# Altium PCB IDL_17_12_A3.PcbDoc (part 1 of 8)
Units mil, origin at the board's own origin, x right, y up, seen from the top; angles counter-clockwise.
Board outline 5119.97 x 10350 mil, 6 copper layers (Top Signal, 3.3 Volt, GND, 5 Volt, Split Plane, Bot Signal), stack 66.2 mil thick; 510 components, 178 nets, 2317 pads, 385 vias.
Unrouted connection lines stored in the file: 1.
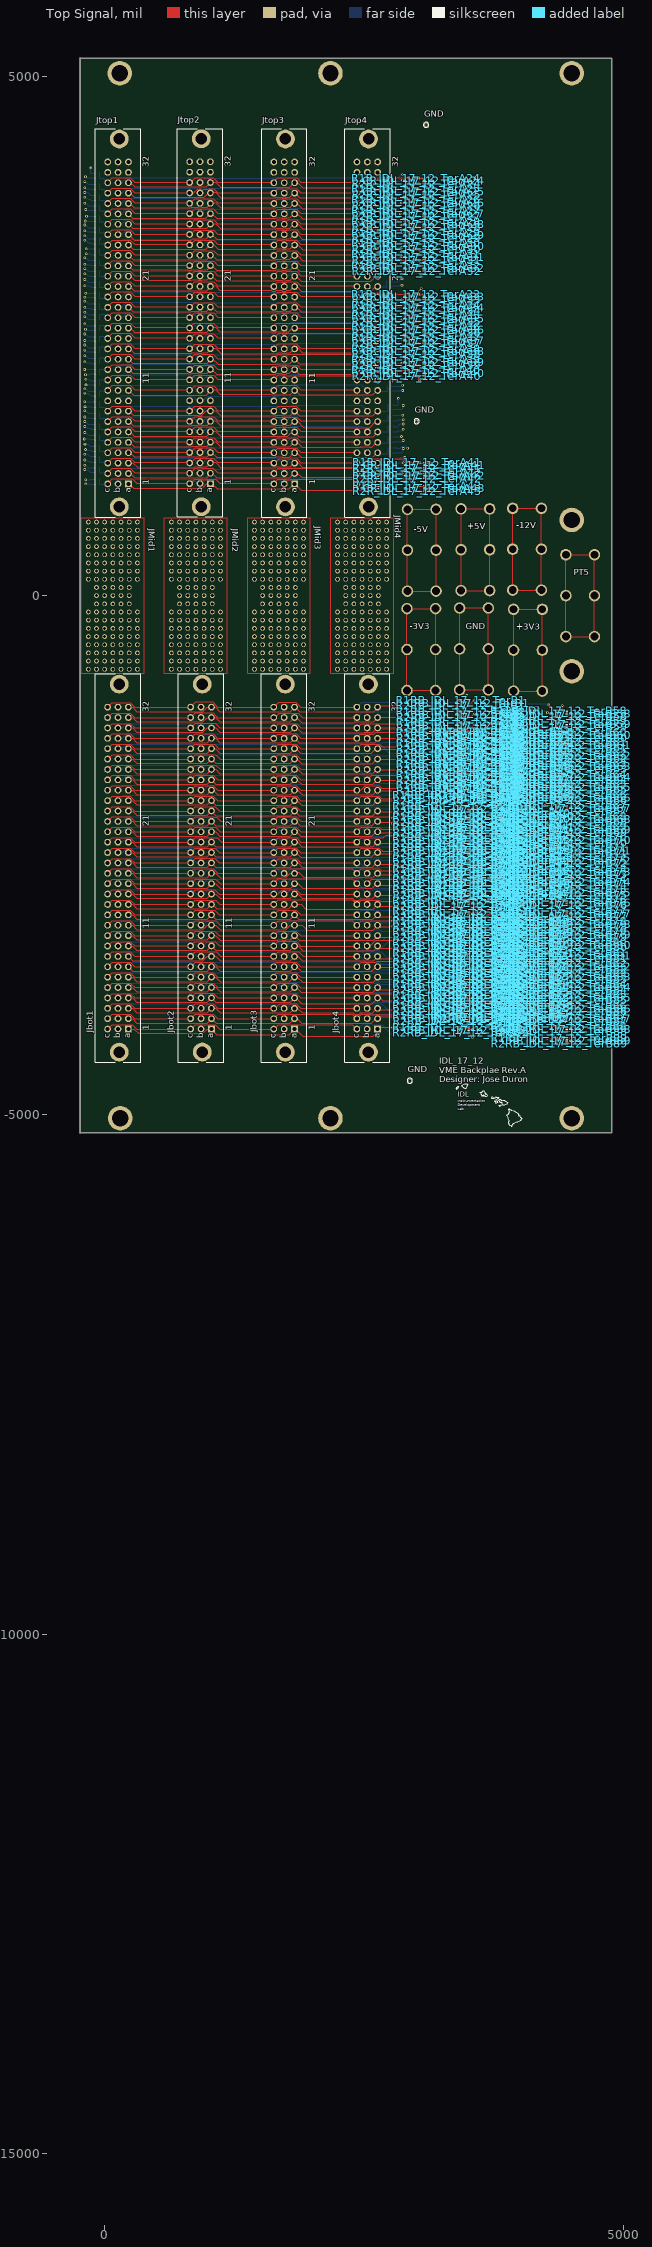
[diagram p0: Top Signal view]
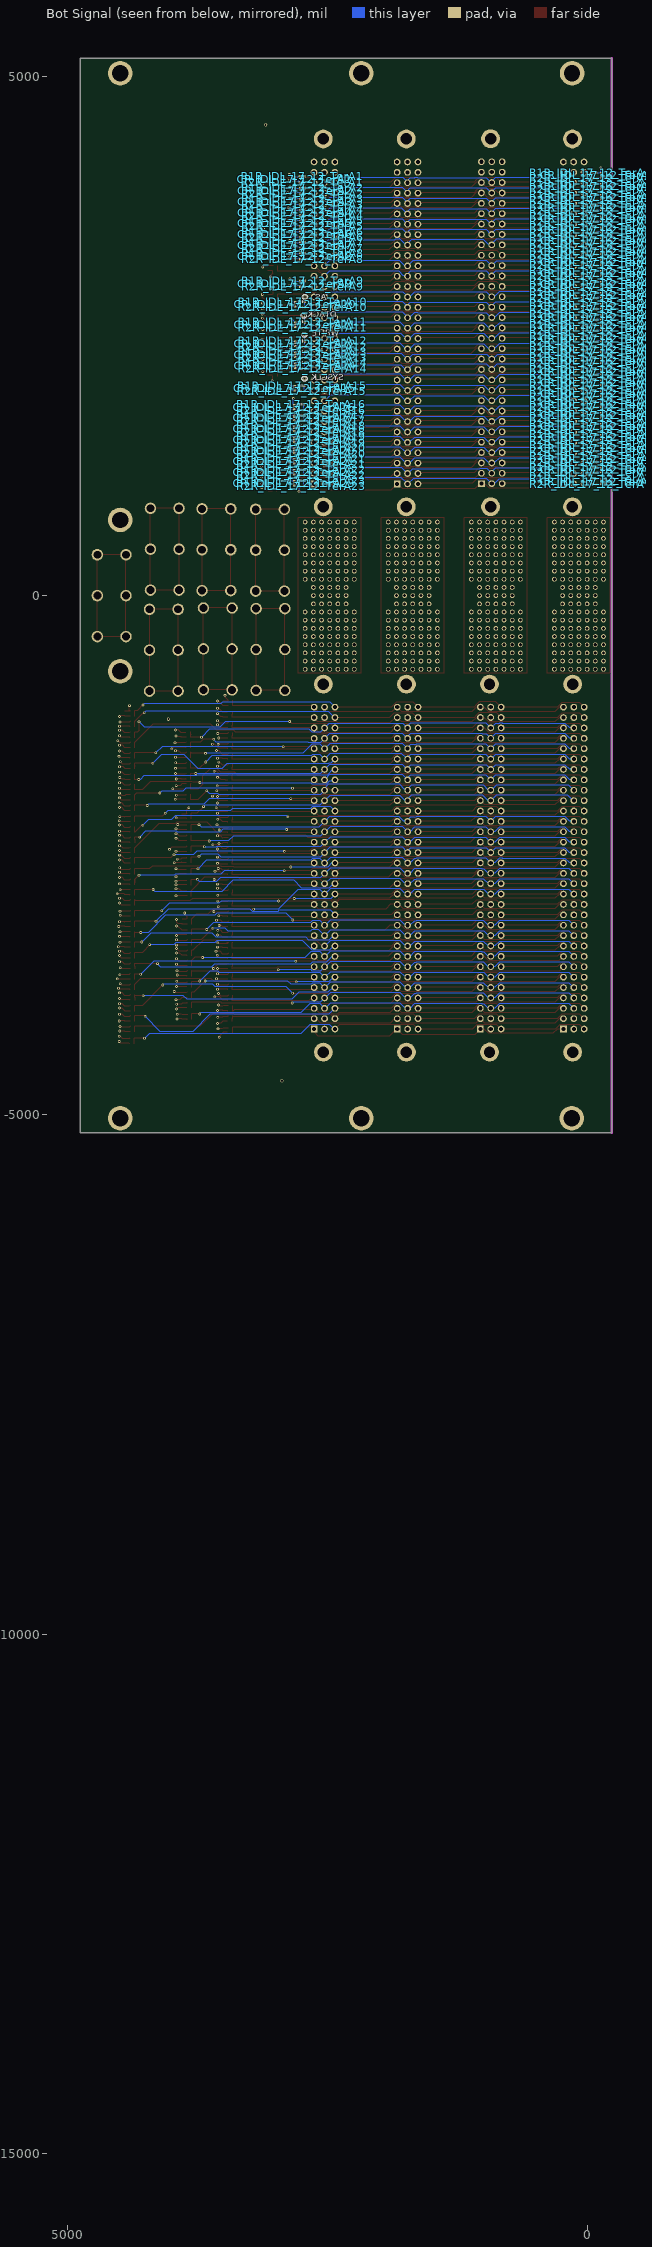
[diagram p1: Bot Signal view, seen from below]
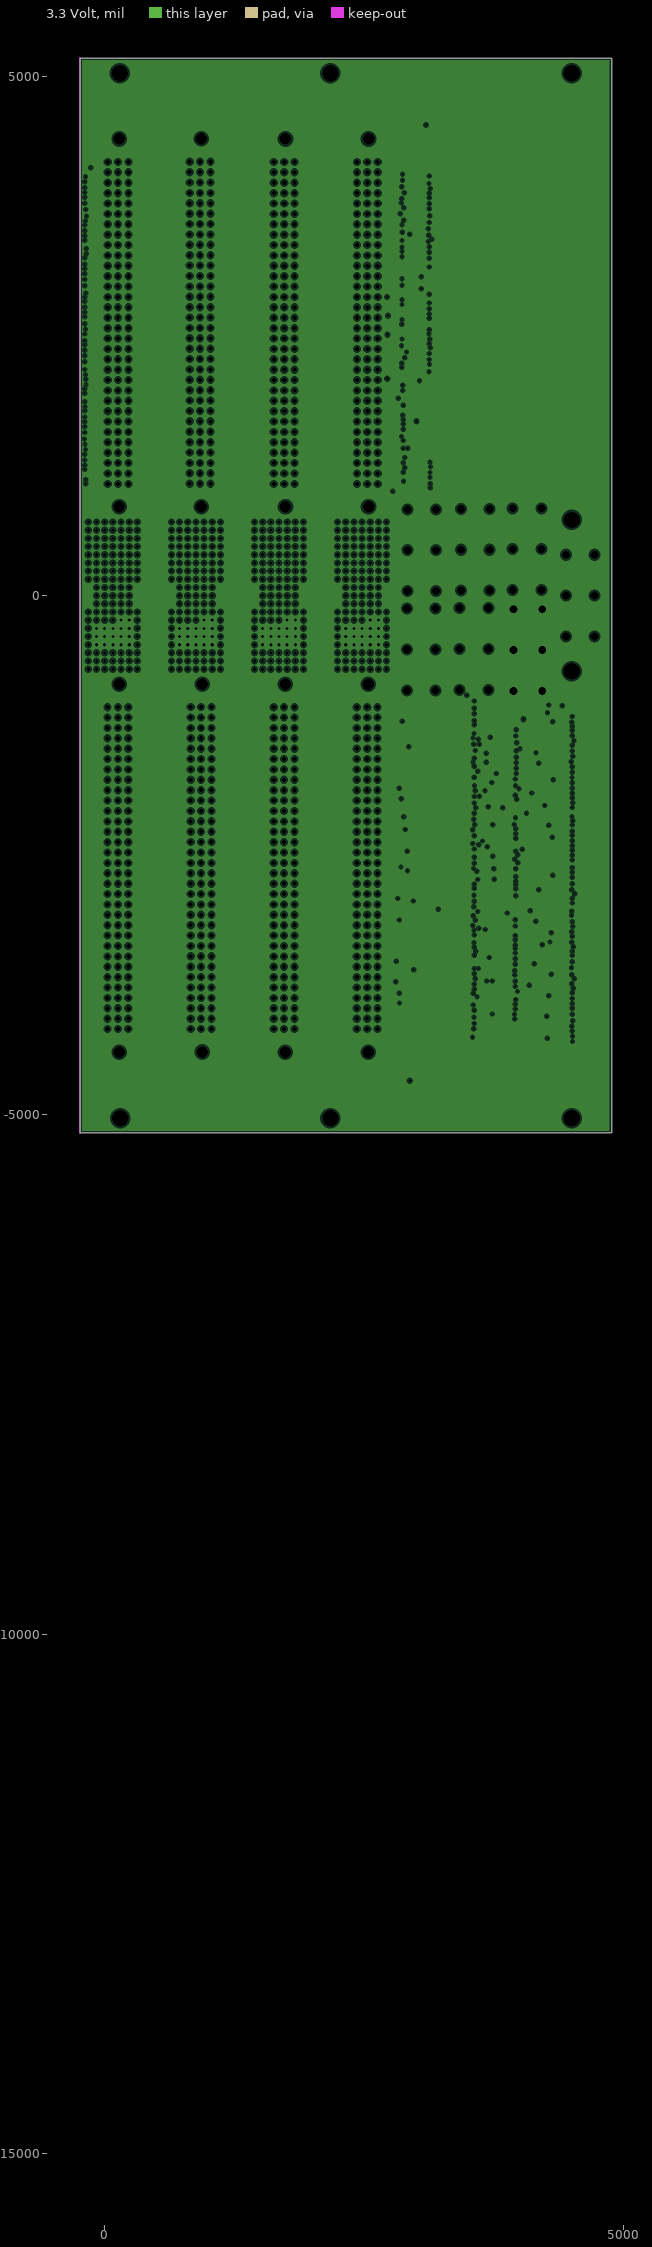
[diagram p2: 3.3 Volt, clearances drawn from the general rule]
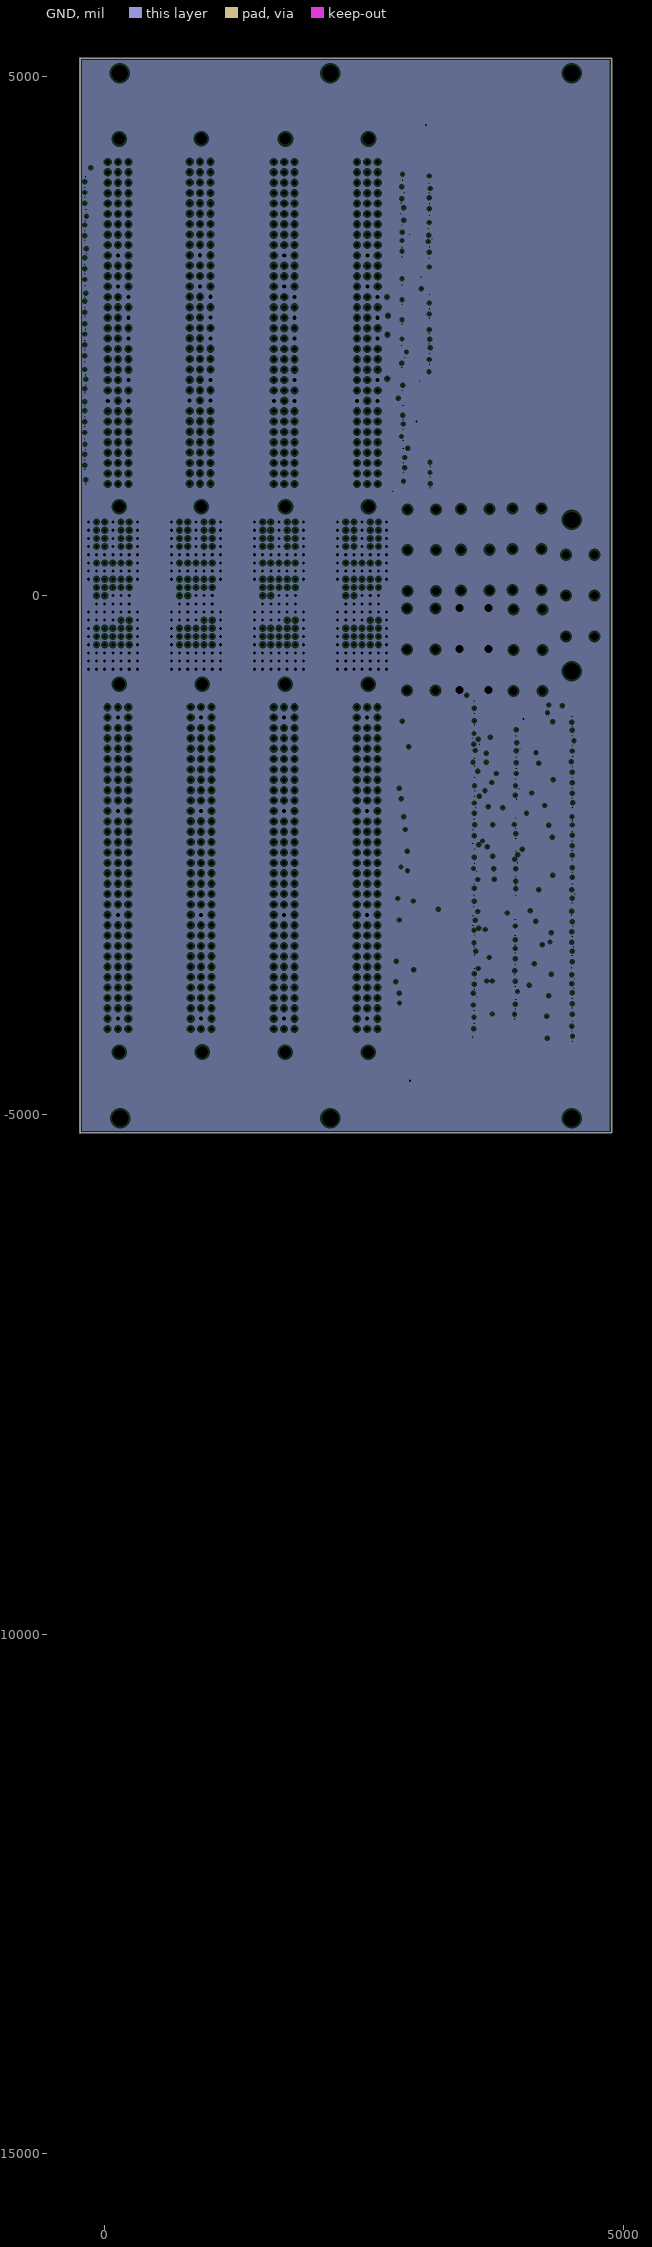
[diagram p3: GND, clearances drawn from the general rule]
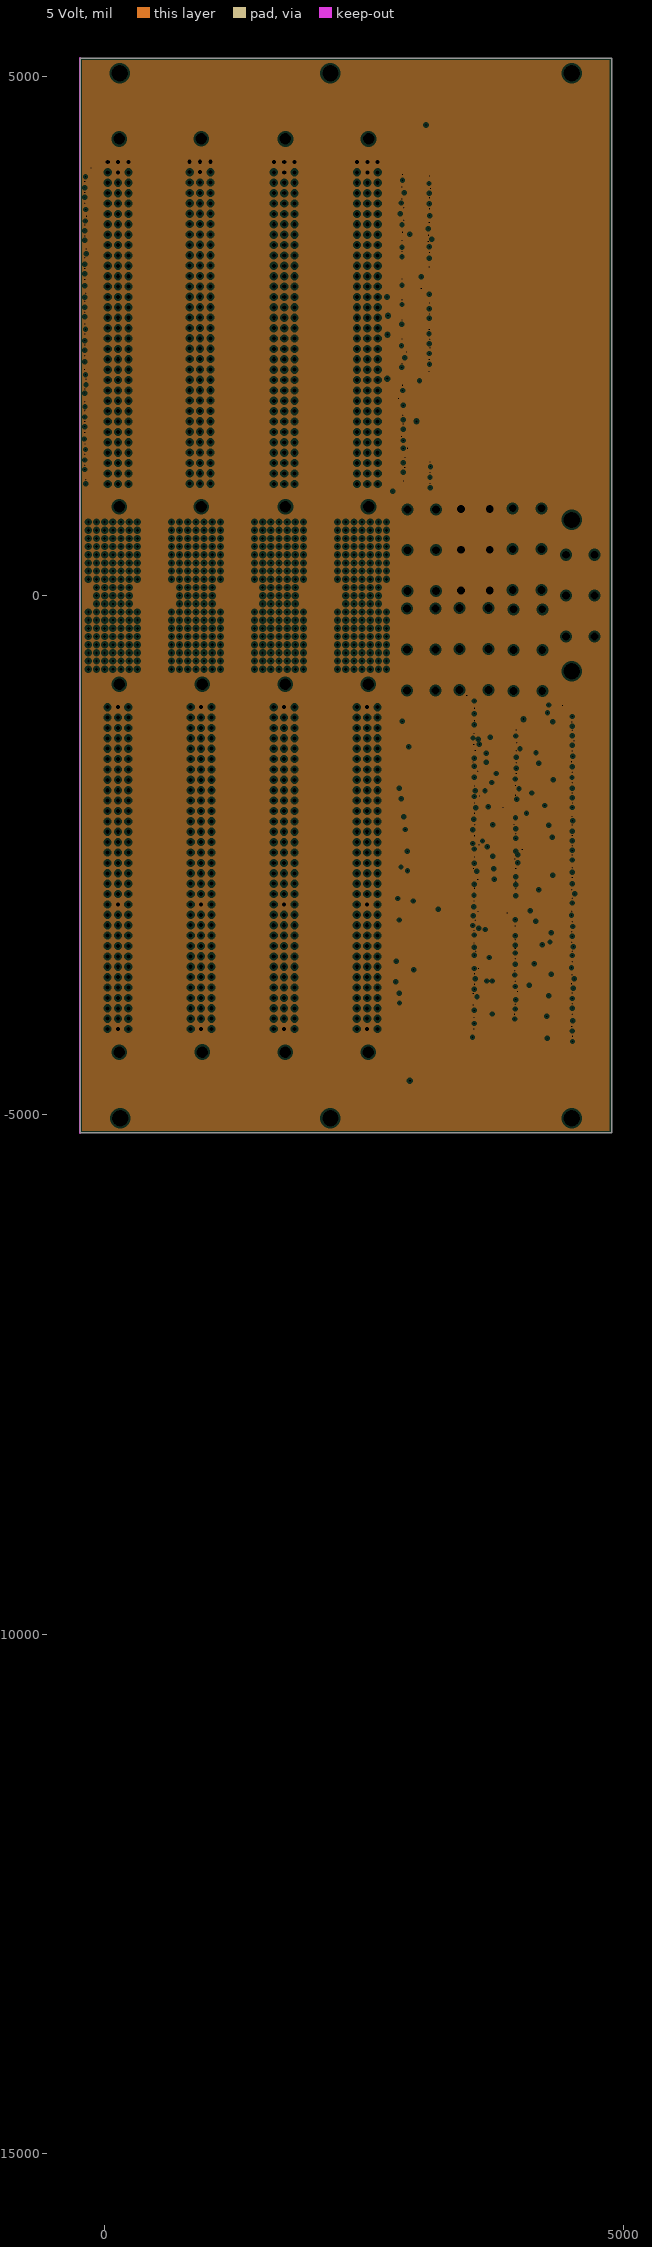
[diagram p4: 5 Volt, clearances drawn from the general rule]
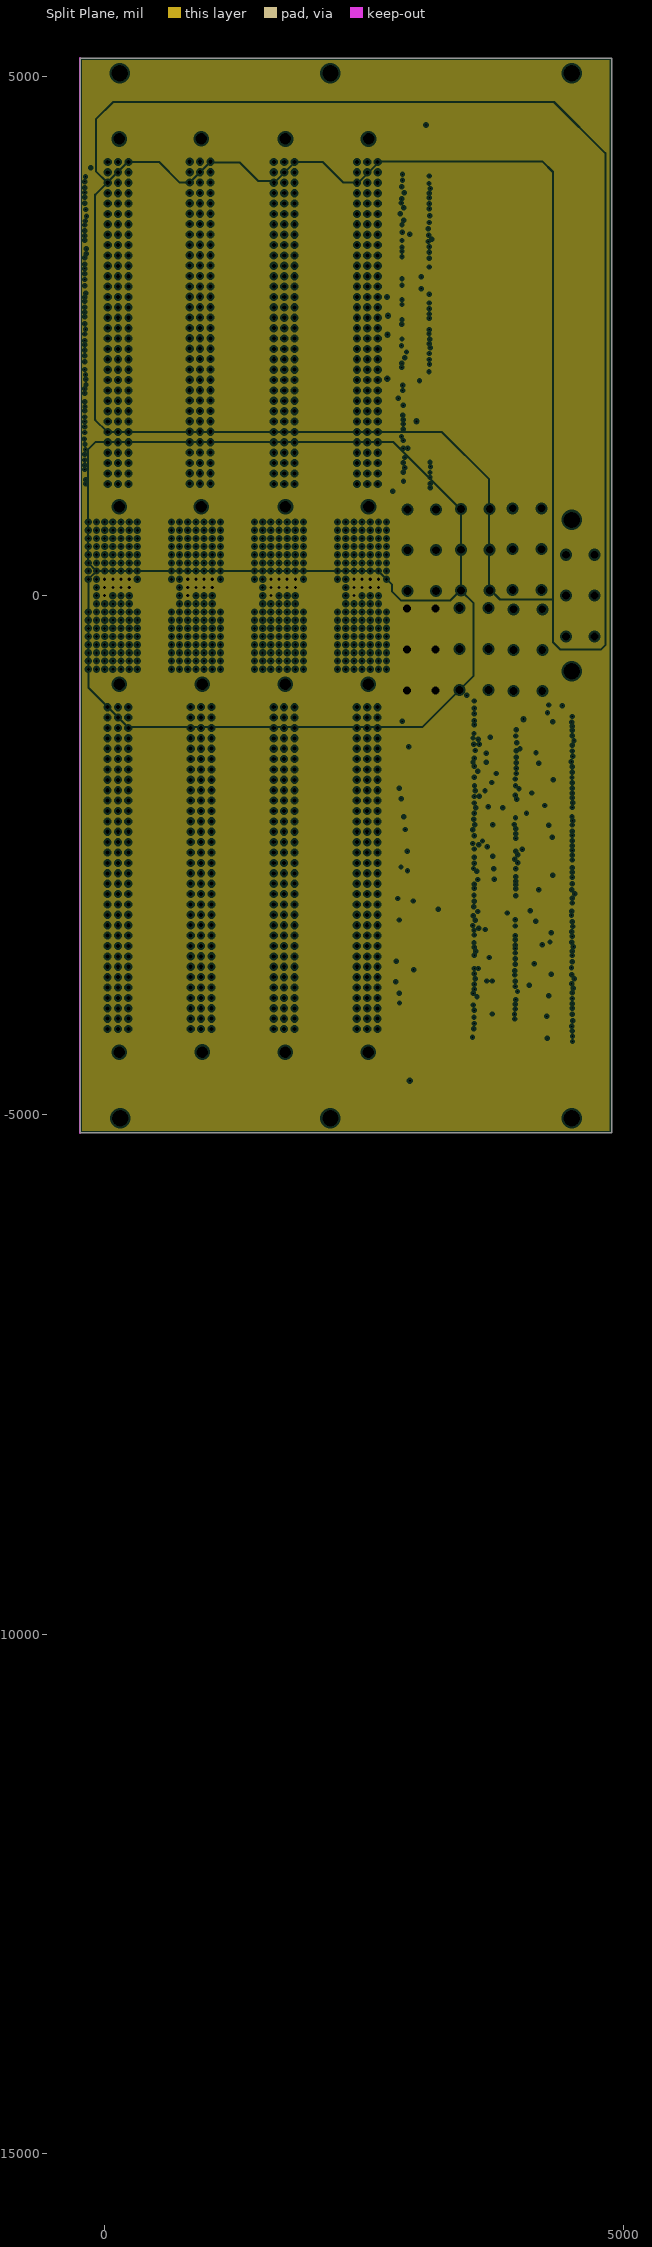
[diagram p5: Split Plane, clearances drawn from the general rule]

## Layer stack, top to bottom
Top Solder: solder mask 0.4, Solder Resist, Dk 3.5
Top Signal: signal copper 2.7
Dielectric 1: core 10, FR-4, Dk 4.2
3.3 Volt: plane copper 2.7, net 3V3
Dielectric2: prepreg 10, FR-4, Dk 4.2
GND: plane copper 2.7, net GND
Dielectric 5: core 10, FR-4, Dk 4.2
5 Volt: plane copper 2.7, net 5V
Dielectric 6: prepreg 10, FR-4, Dk 4.2
Split Plane: plane copper 2.7, net -3V3
Dielectric3: core 10, FR-4, Dk 4.2
Bot Signal: signal copper 2.7
Bottom Solder: solder mask 0.4, Solder Resist, Dk 3.5

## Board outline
-237,5177 4882.97,5177 4882.97,-5173 -237,-5173

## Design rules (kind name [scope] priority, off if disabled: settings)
Clearance "Clearance - Default - DEFAULT- SMD" [IsVia vs IsSMTPin] p1: gap=6 ignorepadtopadclearanceinfootprint=FALSE
Clearance "Clearance - Default - DEFAULT - Via" [IsVia vs IsVia] p2: gap=6 ignorepadtopadclearanceinfootprint=FALSE
Clearance "Clearance - Default - DEFAULT - Net" [All] p3: gap=6 ignorepadtopadclearanceinfootprint=FALSE except(0: Arc-Hole Track-Hole SMDPad-Hole THPad-Hole Via-Hole Fill-Hole Poly-Hole Region-Hole Text-Hole; 10: Text-Text)
ComponentClearance "ComponentClearance - Default - DEFAULT" [All] p1: gap=6 collisioncheckmode=3 verticalgap=10 showdistances=FALSE
DiffPairsRouting [All] p1: maxlimit=10 minlimit=4.02 mostfreqgap=6 toplayer_minwidth=4.02 toplayer_maxwidth=10 toplayer_prefwidth=8 bottomlayer_minwidth=4.02 bottomlayer_maxwidth=10 bottomlayer_prefwidth=8 maxuncoupledlength=500
FanoutControl Fanout_Small [(CompPinCount < 5)] p3: bgadir=Out bgaviamode=Centered fanoutstyle=Auto fanoutdirection=OutThenIn viagrid=1 // Fanout_Small (Default Rule)
FanoutControl Fanout_SOIC [IsSOIC] p4: bgadir=Out bgaviamode=Centered fanoutstyle=Auto fanoutdirection=Alternating viagrid=1 // Fanout_SOIC (Default Rule)
HoleSize [All] p1: absolutevalues=TRUE maxlimit=200 minlimit=1 maxpercent=80.000 minpercent=20.000
HoleToHoleClearance "HoleToHoleClearance - Default - DEFAULT" [All] p1: gap=6 allowstackedmicrovias=TRUE
Length "Default Length" [All] p1: maxlimit=50000 minlimit=0
MaxMinImpedance "Default Impedance" [All] p1: minimum=50.00 maximum=150.0
MinimumSolderMaskSliver [All] p1: minsoldermaskwidth=5
ParallelSegment "Default Parallel Segment Adjasent" [All] p1: limit=1000 gap=200
ParallelSegment "Default Parallel Segment Same Layer" [All] p2: limit=1000 gap=200
PlaneClearance [All] p1: clearance=20
PlaneConnect "Default PlaneConnect" [All] p1: planeconnectstyle=Direct reliefexpansion=20 reliefentries=4 reliefconductorwidth=15 reliefairgap=10
PolygonConnect "PolygonConnect - Default SMT" [IsSMTPin] p1: connectstyle=Relief reliefconductorwidth=10 reliefentries=4 polygonreliefangle="45 Angle" airgapwidth=10
PolygonConnect "PolygonConnect - Default Pad" [All] p2: connectstyle=Relief reliefconductorwidth=15 reliefentries=4 polygonreliefangle="45 Angle" airgapwidth=10
RoomDefinition IDL_17_12_TerA72 [InComponentClass('IDL_17_12_TerA72')] p1 off: confinementstyle=ConfineIn formatcopy=TRUE lockcomponents=FALSE outline 5150.72,878.23 5314.5,878.23 5314.5,997.65 5150.72,997.65
RoomDefinition IDL_17_12_TerB89 [InComponentClass('IDL_17_12_TerB89')] p2 off: confinementstyle=ConfineIn formatcopy=TRUE lockcomponents=TRUE outline 5340.67,-4332.36 5485.36,-4332.36 5485.36,-4220.91 5340.67,-4220.91
RoomDefinition IDL_17_12_TerB88 [InComponentClass('IDL_17_12_TerB88')] p3 off: confinementstyle=ConfineIn formatcopy=TRUE lockcomponents=FALSE outline 5340,-4106.02 5488.48,-4106.02 5488.48,-4214.48 5340,-4214.48
RoomDefinition IDL_17_12_TerB87 [InComponentClass('IDL_17_12_TerB87')] p4 off: confinementstyle=ConfineIn formatcopy=TRUE lockcomponents=FALSE outline 5340,-4006.02 5488.48,-4006.02 5488.48,-4114.48 5340,-4114.48
RoomDefinition IDL_17_12_TerB86 [InComponentClass('IDL_17_12_TerB86')] p5 off: confinementstyle=ConfineIn formatcopy=TRUE lockcomponents=FALSE outline 5340,-3906.02 5488.48,-3906.02 5488.48,-4014.48 5340,-4014.48
RoomDefinition IDL_17_12_TerB85 [InComponentClass('IDL_17_12_TerB85')] p6 off: confinementstyle=ConfineIn formatcopy=TRUE lockcomponents=FALSE outline 5340,-3801.02 5488.48,-3801.02 5488.48,-3909.48 5340,-3909.48
RoomDefinition IDL_17_12_TerB84 [InComponentClass('IDL_17_12_TerB84')] p7 off: confinementstyle=ConfineIn formatcopy=TRUE lockcomponents=FALSE outline 5340,-3701.02 5488.48,-3701.02 5488.48,-3809.48 5340,-3809.48
RoomDefinition IDL_17_12_TerB83 [InComponentClass('IDL_17_12_TerB83')] p8 off: confinementstyle=ConfineIn formatcopy=TRUE lockcomponents=FALSE outline 5340,-3601.02 5488.48,-3601.02 5488.48,-3709.48 5340,-3709.48
RoomDefinition IDL_17_12_TerB82 [InComponentClass('IDL_17_12_TerB82')] p9 off: confinementstyle=ConfineIn formatcopy=TRUE lockcomponents=FALSE outline 5340,-3501.02 5488.48,-3501.02 5488.48,-3609.48 5340,-3609.48
RoomDefinition IDL_17_12_TerB81 [InComponentClass('IDL_17_12_TerB81')] p10 off: confinementstyle=ConfineIn formatcopy=TRUE lockcomponents=FALSE outline 5340,-3399.02 5488.48,-3399.02 5488.48,-3507.48 5340,-3507.48
RoomDefinition IDL_17_12_TerB80 [InComponentClass('IDL_17_12_TerB80')] p11 off: confinementstyle=ConfineIn formatcopy=TRUE lockcomponents=FALSE outline 5340,-3294.02 5488.48,-3294.02 5488.48,-3402.48 5340,-3402.48
RoomDefinition IDL_17_12_TerB79 [InComponentClass('IDL_17_12_TerB79')] p12 off: confinementstyle=ConfineIn formatcopy=TRUE lockcomponents=FALSE outline 5340,-3194.02 5488.48,-3194.02 5488.48,-3302.48 5340,-3302.48
RoomDefinition IDL_17_12_TerB78 [InComponentClass('IDL_17_12_TerB78')] p13 off: confinementstyle=ConfineIn formatcopy=TRUE lockcomponents=FALSE outline 5340,-3094.02 5488.48,-3094.02 5488.48,-3202.48 5340,-3202.48
RoomDefinition IDL_17_12_TerB77 [InComponentClass('IDL_17_12_TerB77')] p14 off: confinementstyle=ConfineIn formatcopy=TRUE lockcomponents=FALSE outline 5340,-2994.02 5488.48,-2994.02 5488.48,-3102.48 5340,-3102.48
RoomDefinition IDL_17_12_TerB76 [InComponentClass('IDL_17_12_TerB76')] p15 off: confinementstyle=ConfineIn formatcopy=TRUE lockcomponents=FALSE outline 5340,-2889.02 5488.48,-2889.02 5488.48,-2997.48 5340,-2997.48
RoomDefinition IDL_17_12_TerB75 [InComponentClass('IDL_17_12_TerB75')] p16 off: confinementstyle=ConfineIn formatcopy=TRUE lockcomponents=FALSE outline 5340,-2789.02 5488.48,-2789.02 5488.48,-2897.48 5340,-2897.48
RoomDefinition IDL_17_12_TerB74 [InComponentClass('IDL_17_12_TerB74')] p17 off: confinementstyle=ConfineIn formatcopy=TRUE lockcomponents=FALSE outline 5340,-2689.02 5488.48,-2689.02 5488.48,-2797.48 5340,-2797.48
RoomDefinition IDL_17_12_TerB73 [InComponentClass('IDL_17_12_TerB73')] p18 off: confinementstyle=ConfineIn formatcopy=TRUE lockcomponents=FALSE outline 5340,-2589.02 5488.48,-2589.02 5488.48,-2697.48 5340,-2697.48
RoomDefinition IDL_17_12_TerB72 [InComponentClass('IDL_17_12_TerB72')] p19 off: confinementstyle=ConfineIn formatcopy=TRUE lockcomponents=FALSE outline 5340,-2484.02 5488.48,-2484.02 5488.48,-2592.48 5340,-2592.48
RoomDefinition IDL_17_12_TerB71 [InComponentClass('IDL_17_12_TerB71')] p20 off: confinementstyle=ConfineIn formatcopy=TRUE lockcomponents=FALSE outline 5340,-2384.02 5488.48,-2384.02 5488.48,-2492.48 5340,-2492.48
RoomDefinition IDL_17_12_TerB70 [InComponentClass('IDL_17_12_TerB70')] p21 off: confinementstyle=ConfineIn formatcopy=TRUE lockcomponents=FALSE outline 5340,-2284.02 5488.48,-2284.02 5488.48,-2392.48 5340,-2392.48
RoomDefinition IDL_17_12_TerB69 [InComponentClass('IDL_17_12_TerB69')] p22 off: confinementstyle=ConfineIn formatcopy=TRUE lockcomponents=FALSE outline 5340,-2184.02 5488.48,-2184.02 5488.48,-2292.48 5340,-2292.48
RoomDefinition IDL_17_12_TerB68 [InComponentClass('IDL_17_12_TerB68')] p23 off: confinementstyle=ConfineIn formatcopy=TRUE lockcomponents=FALSE outline 5340,-2084.02 5488.48,-2084.02 5488.48,-2192.48 5340,-2192.48
RoomDefinition IDL_17_12_TerB67 [InComponentClass('IDL_17_12_TerB67')] p24 off: confinementstyle=ConfineIn formatcopy=TRUE lockcomponents=FALSE outline 5340,-1979.02 5488.48,-1979.02 5488.48,-2087.48 5340,-2087.48
RoomDefinition IDL_17_12_TerB66 [InComponentClass('IDL_17_12_TerB66')] p25 off: confinementstyle=ConfineIn formatcopy=TRUE lockcomponents=FALSE outline 5340,-1877.02 5488.48,-1877.02 5488.48,-1985.48 5340,-1985.48
RoomDefinition IDL_17_12_TerB65 [InComponentClass('IDL_17_12_TerB65')] p26 off: confinementstyle=ConfineIn formatcopy=TRUE lockcomponents=FALSE outline 5340,-1777.02 5488.48,-1777.02 5488.48,-1885.48 5340,-1885.48
RoomDefinition IDL_17_12_TerB64 [InComponentClass('IDL_17_12_TerB64')] p27 off: confinementstyle=ConfineIn formatcopy=TRUE lockcomponents=FALSE outline 5340,-1677.02 5488.48,-1677.02 5488.48,-1785.48 5340,-1785.48
RoomDefinition IDL_17_12_TerB63 [InComponentClass('IDL_17_12_TerB63')] p28 off: confinementstyle=ConfineIn formatcopy=TRUE lockcomponents=FALSE outline 5340,-1572.02 5488.48,-1572.02 5488.48,-1680.48 5340,-1680.48
RoomDefinition IDL_17_12_TerB62 [InComponentClass('IDL_17_12_TerB62')] p29 off: confinementstyle=ConfineIn formatcopy=TRUE lockcomponents=FALSE outline 5340,-1472.02 5488.48,-1472.02 5488.48,-1580.48 5340,-1580.48
RoomDefinition IDL_17_12_TerB61 [InComponentClass('IDL_17_12_TerB61')] p30 off: confinementstyle=ConfineIn formatcopy=TRUE lockcomponents=FALSE outline 5340,-1372.02 5488.48,-1372.02 5488.48,-1480.48 5340,-1480.48
RoomDefinition IDL_17_12_TerB60 [InComponentClass('IDL_17_12_TerB60')] p31 off: confinementstyle=ConfineIn formatcopy=TRUE lockcomponents=FALSE outline 5340,-1272.02 5488.48,-1272.02 5488.48,-1380.48 5340,-1380.48
RoomDefinition IDL_17_12_TerB59 [InComponentClass('IDL_17_12_TerB59')] p32 off: confinementstyle=ConfineIn formatcopy=TRUE lockcomponents=FALSE outline 5340,-1167.02 5488.48,-1167.02 5488.48,-1275.48 5340,-1275.48
RoomDefinition IDL_17_12_TerB58 [InComponentClass('IDL_17_12_TerB58')] p33 off: confinementstyle=ConfineIn formatcopy=TRUE lockcomponents=FALSE outline 5340,-1067.02 5488.48,-1067.02 5488.48,-1175.48 5340,-1175.48
RoomDefinition IDL_17_12_TerB57 [InComponentClass('IDL_17_12_TerB57')] p34 off: confinementstyle=ConfineIn formatcopy=TRUE lockcomponents=FALSE outline 4214.96,-4011.52 4363.44,-4011.52 4363.44,-4119.98 4214.96,-4119.98
RoomDefinition IDL_17_12_TerB56 [InComponentClass('IDL_17_12_TerB56')] p35 off: confinementstyle=ConfineIn formatcopy=TRUE lockcomponents=FALSE outline 4215,-3900.54 4363.48,-3900.54 4363.48,-4009 4215,-4009
RoomDefinition IDL_17_12_TerB55 [InComponentClass('IDL_17_12_TerB55')] p36 off: confinementstyle=ConfineIn formatcopy=TRUE lockcomponents=FALSE outline 4215,-3800.54 4363.48,-3800.54 4363.48,-3909 4215,-3909
RoomDefinition IDL_17_12_TerB54 [InComponentClass('IDL_17_12_TerB54')] p37 off: confinementstyle=ConfineIn formatcopy=TRUE lockcomponents=FALSE outline 4215,-3700.54 4363.48,-3700.54 4363.48,-3809 4215,-3809
RoomDefinition IDL_17_12_TerB53 [InComponentClass('IDL_17_12_TerB53')] p38 off: confinementstyle=ConfineIn formatcopy=TRUE lockcomponents=FALSE outline 4215,-3595.54 4363.48,-3595.54 4363.48,-3704 4215,-3704
RoomDefinition IDL_17_12_TerB52 [InComponentClass('IDL_17_12_TerB52')] p39 off: confinementstyle=ConfineIn formatcopy=TRUE lockcomponents=FALSE outline 4215,-3495.54 4363.48,-3495.54 4363.48,-3604 4215,-3604
RoomDefinition IDL_17_12_TerB51 [InComponentClass('IDL_17_12_TerB51')] p40 off: confinementstyle=ConfineIn formatcopy=TRUE lockcomponents=FALSE outline 4215,-3397.54 4363.48,-3397.54 4363.48,-3506 4215,-3506
RoomDefinition IDL_17_12_TerB50 [InComponentClass('IDL_17_12_TerB50')] p41 off: confinementstyle=ConfineIn formatcopy=TRUE lockcomponents=FALSE outline 4215,-3297.54 4363.48,-3297.54 4363.48,-3406 4215,-3406
RoomDefinition IDL_17_12_TerB49 [InComponentClass('IDL_17_12_TerB49')] p42 off: confinementstyle=ConfineIn formatcopy=TRUE lockcomponents=FALSE outline 4215,-3197.54 4363.48,-3197.54 4363.48,-3306 4215,-3306
RoomDefinition IDL_17_12_TerB48 [InComponentClass('IDL_17_12_TerB48')] p43 off: confinementstyle=ConfineIn formatcopy=TRUE lockcomponents=FALSE outline 4215,-3092.54 4363.48,-3092.54 4363.48,-3201 4215,-3201
RoomDefinition IDL_17_12_TerB47 [InComponentClass('IDL_17_12_TerB47')] p44 off: confinementstyle=ConfineIn formatcopy=TRUE lockcomponents=FALSE outline 4220,-2822.54 4368.48,-2822.54 4368.48,-2931 4220,-2931
RoomDefinition IDL_17_12_TerB46 [InComponentClass('IDL_17_12_TerB46')] p45 off: confinementstyle=ConfineIn formatcopy=TRUE lockcomponents=FALSE outline 4220,-2717.54 4368.48,-2717.54 4368.48,-2826 4220,-2826
RoomDefinition IDL_17_12_TerB45 [InComponentClass('IDL_17_12_TerB45')] p46 off: confinementstyle=ConfineIn formatcopy=TRUE lockcomponents=FALSE outline 4220,-2612.54 4368.48,-2612.54 4368.48,-2721 4220,-2721
RoomDefinition IDL_17_12_TerB44 [InComponentClass('IDL_17_12_TerB44')] p47 off: confinementstyle=ConfineIn formatcopy=TRUE lockcomponents=FALSE outline 4220,-2502.54 4368.48,-2502.54 4368.48,-2611 4220,-2611
RoomDefinition IDL_17_12_TerB43 [InComponentClass('IDL_17_12_TerB43')] p48 off: confinementstyle=ConfineIn formatcopy=TRUE lockcomponents=FALSE outline 4220,-2397.54 4368.48,-2397.54 4368.48,-2506 4220,-2506
RoomDefinition IDL_17_12_TerB42 [InComponentClass('IDL_17_12_TerB42')] p49 off: confinementstyle=ConfineIn formatcopy=TRUE lockcomponents=FALSE outline 4220,-2292.54 4368.48,-2292.54 4368.48,-2401 4220,-2401
RoomDefinition IDL_17_12_TerB41 [InComponentClass('IDL_17_12_TerB41')] p50 off: confinementstyle=ConfineIn formatcopy=TRUE lockcomponents=FALSE outline 4220,-2187.54 4368.48,-2187.54 4368.48,-2296 4220,-2296
RoomDefinition IDL_17_12_TerB40 [InComponentClass('IDL_17_12_TerB40')] p51 off: confinementstyle=ConfineIn formatcopy=TRUE lockcomponents=FALSE outline 4220,-2077.54 4368.48,-2077.54 4368.48,-2186 4220,-2186
RoomDefinition IDL_17_12_TerB39 [InComponentClass('IDL_17_12_TerB39')] p52 off: confinementstyle=ConfineIn formatcopy=TRUE lockcomponents=FALSE outline 4225,-1895.89 4373.48,-1895.89 4373.48,-2004.35 4225,-2004.35
RoomDefinition IDL_17_12_TerB38 [InComponentClass('IDL_17_12_TerB38')] p53 off: confinementstyle=ConfineIn formatcopy=TRUE lockcomponents=FALSE outline 4225,-1795.89 4373.48,-1795.89 4373.48,-1904.35 4225,-1904.35
RoomDefinition IDL_17_12_TerB37 [InComponentClass('IDL_17_12_TerB37')] p54 off: confinementstyle=ConfineIn formatcopy=TRUE lockcomponents=FALSE outline 4225,-1695.89 4373.48,-1695.89 4373.48,-1804.35 4225,-1804.35
RoomDefinition IDL_17_12_TerB36 [InComponentClass('IDL_17_12_TerB36')] p55 off: confinementstyle=ConfineIn formatcopy=TRUE lockcomponents=FALSE outline 4225,-1592.89 4373.48,-1592.89 4373.48,-1701.35 4225,-1701.35
RoomDefinition IDL_17_12_TerB35 [InComponentClass('IDL_17_12_TerB35')] p56 off: confinementstyle=ConfineIn formatcopy=TRUE lockcomponents=FALSE outline 4225,-1492.89 4373.48,-1492.89 4373.48,-1601.35 4225,-1601.35
RoomDefinition IDL_17_12_TerB34 [InComponentClass('IDL_17_12_TerB34')] p57 off: confinementstyle=ConfineIn formatcopy=TRUE lockcomponents=FALSE outline 4225,-1392.89 4373.48,-1392.89 4373.48,-1501.35 4225,-1501.35
RoomDefinition IDL_17_12_TerB33 [InComponentClass('IDL_17_12_TerB33')] p58 off: confinementstyle=ConfineIn formatcopy=TRUE lockcomponents=FALSE outline 4225,-1292.89 4373.48,-1292.89 4373.48,-1401.35 4225,-1401.35
RoomDefinition IDL_17_12_TerB32 [InComponentClass('IDL_17_12_TerB32')] p59 off: confinementstyle=ConfineIn formatcopy=TRUE lockcomponents=FALSE outline 3384.6,-4128.6 3533.08,-4128.6 3533.08,-4237.06 3384.6,-4237.06
RoomDefinition IDL_17_12_TerB31 [InComponentClass('IDL_17_12_TerB31')] p60 off: confinementstyle=ConfineIn formatcopy=TRUE lockcomponents=FALSE outline 3385,-4019.54 3533.48,-4019.54 3533.48,-4128 3385,-4128
RoomDefinition IDL_17_12_TerB30 [InComponentClass('IDL_17_12_TerB30')] p61 off: confinementstyle=ConfineIn formatcopy=TRUE lockcomponents=FALSE outline 3385,-3919.54 3533.48,-3919.54 3533.48,-4028 3385,-4028
RoomDefinition IDL_17_12_TerB29 [InComponentClass('IDL_17_12_TerB29')] p62 off: confinementstyle=ConfineIn formatcopy=TRUE lockcomponents=FALSE outline 3385,-3819.54 3533.48,-3819.54 3533.48,-3928 3385,-3928
RoomDefinition IDL_17_12_TerB28 [InComponentClass('IDL_17_12_TerB28')] p63 off: confinementstyle=ConfineIn formatcopy=TRUE lockcomponents=FALSE outline 3385,-3714.54 3533.48,-3714.54 3533.48,-3823 3385,-3823
RoomDefinition IDL_17_12_TerB27 [InComponentClass('IDL_17_12_TerB27')] p64 off: confinementstyle=ConfineIn formatcopy=TRUE lockcomponents=FALSE outline 3385,-3614.54 3533.48,-3614.54 3533.48,-3723 3385,-3723
RoomDefinition IDL_17_12_TerB26 [InComponentClass('IDL_17_12_TerB26')] p65 off: confinementstyle=ConfineIn formatcopy=TRUE lockcomponents=FALSE outline 3385,-3514.54 3533.48,-3514.54 3533.48,-3623 3385,-3623
RoomDefinition IDL_17_12_TerB25 [InComponentClass('IDL_17_12_TerB25')] p66 off: confinementstyle=ConfineIn formatcopy=TRUE lockcomponents=FALSE outline 3385,-3414.54 3533.48,-3414.54 3533.48,-3523 3385,-3523
RoomDefinition IDL_17_12_TerB24 [InComponentClass('IDL_17_12_TerB24')] p67 off: confinementstyle=ConfineIn formatcopy=TRUE lockcomponents=FALSE outline 3385,-3314.54 3533.48,-3314.54 3533.48,-3423 3385,-3423
RoomDefinition IDL_17_12_TerB23 [InComponentClass('IDL_17_12_TerB23')] p68 off: confinementstyle=ConfineIn formatcopy=TRUE lockcomponents=FALSE outline 3385,-3209.54 3533.48,-3209.54 3533.48,-3318 3385,-3318
RoomDefinition IDL_17_12_TerB22 [InComponentClass('IDL_17_12_TerB22')] p69 off: confinementstyle=ConfineIn formatcopy=TRUE lockcomponents=FALSE outline 3385,-3109.54 3533.48,-3109.54 3533.48,-3218 3385,-3218
RoomDefinition IDL_17_12_TerB21 [InComponentClass('IDL_17_12_TerB21')] p70 off: confinementstyle=ConfineIn formatcopy=TRUE lockcomponents=FALSE outline 3385,-3011.54 3533.48,-3011.54 3533.48,-3120 3385,-3120
RoomDefinition IDL_17_12_TerB20 [InComponentClass('IDL_17_12_TerB20')] p71 off: confinementstyle=ConfineIn formatcopy=TRUE lockcomponents=FALSE outline 3385,-2911.54 3533.48,-2911.54 3533.48,-3020 3385,-3020
RoomDefinition IDL_17_12_TerB19 [InComponentClass('IDL_17_12_TerB19')] p72 off: confinementstyle=ConfineIn formatcopy=TRUE lockcomponents=FALSE outline 3385,-2806.54 3533.48,-2806.54 3533.48,-2915 3385,-2915
RoomDefinition IDL_17_12_TerB18 [InComponentClass('IDL_17_12_TerB18')] p73 off: confinementstyle=ConfineIn formatcopy=TRUE lockcomponents=FALSE outline 3385,-2706.54 3533.48,-2706.54 3533.48,-2815 3385,-2815
RoomDefinition IDL_17_12_TerB17 [InComponentClass('IDL_17_12_TerB17')] p74 off: confinementstyle=ConfineIn formatcopy=TRUE lockcomponents=FALSE outline 3385,-2606.54 3533.48,-2606.54 3533.48,-2715 3385,-2715
RoomDefinition IDL_17_12_TerB16 [InComponentClass('IDL_17_12_TerB16')] p75 off: confinementstyle=ConfineIn formatcopy=TRUE lockcomponents=FALSE outline 3385,-2506.54 3533.48,-2506.54 3533.48,-2615 3385,-2615
RoomDefinition IDL_17_12_TerB15 [InComponentClass('IDL_17_12_TerB15')] p76 off: confinementstyle=ConfineIn formatcopy=TRUE lockcomponents=FALSE outline 3385,-2401.54 3533.48,-2401.54 3533.48,-2510 3385,-2510
RoomDefinition IDL_17_12_TerB14 [InComponentClass('IDL_17_12_TerB14')] p77 off: confinementstyle=ConfineIn formatcopy=TRUE lockcomponents=FALSE outline 3385,-2301.54 3533.48,-2301.54 3533.48,-2410 3385,-2410
RoomDefinition IDL_17_12_TerB13 [InComponentClass('IDL_17_12_TerB13')] p78 off: confinementstyle=ConfineIn formatcopy=TRUE lockcomponents=FALSE outline 3385,-2201.54 3533.48,-2201.54 3533.48,-2310 3385,-2310
RoomDefinition IDL_17_12_TerB12 [InComponentClass('IDL_17_12_TerB12')] p79 off: confinementstyle=ConfineIn formatcopy=TRUE lockcomponents=FALSE outline 3385,-2101.54 3533.48,-2101.54 3533.48,-2210 3385,-2210
RoomDefinition IDL_17_12_TerB11 [InComponentClass('IDL_17_12_TerB11')] p80 off: confinementstyle=ConfineIn formatcopy=TRUE lockcomponents=FALSE outline 3385,-2001.54 3533.48,-2001.54 3533.48,-2110 3385,-2110
RoomDefinition IDL_17_12_TerB10 [InComponentClass('IDL_17_12_TerB10')] p81 off: confinementstyle=ConfineIn formatcopy=TRUE lockcomponents=FALSE outline 3385,-1896.54 3533.48,-1896.54 3533.48,-2005 3385,-2005
RoomDefinition IDL_17_12_TerB9 [InComponentClass('IDL_17_12_TerB9')] p82 off: confinementstyle=ConfineIn formatcopy=TRUE lockcomponents=FALSE outline 3385,-1796.54 3533.48,-1796.54 3533.48,-1905 3385,-1905
RoomDefinition IDL_17_12_TerB8 [InComponentClass('IDL_17_12_TerB8')] p83 off: confinementstyle=ConfineIn formatcopy=TRUE lockcomponents=FALSE outline 3385,-1696.54 3533.48,-1696.54 3533.48,-1805 3385,-1805
RoomDefinition IDL_17_12_TerB7 [InComponentClass('IDL_17_12_TerB7')] p84 off: confinementstyle=ConfineIn formatcopy=TRUE lockcomponents=FALSE outline 3385,-1596.54 3533.48,-1596.54 3533.48,-1705 3385,-1705
RoomDefinition IDL_17_12_TerB6 [InComponentClass('IDL_17_12_TerB6')] p85 off: confinementstyle=ConfineIn formatcopy=TRUE lockcomponents=FALSE outline 3385,-1493.54 3533.48,-1493.54 3533.48,-1602 3385,-1602
RoomDefinition IDL_17_12_TerB5 [InComponentClass('IDL_17_12_TerB5')] p86 off: confinementstyle=ConfineIn formatcopy=TRUE lockcomponents=FALSE outline 3385,-1393.54 3533.48,-1393.54 3533.48,-1502 3385,-1502
RoomDefinition IDL_17_12_TerB4 [InComponentClass('IDL_17_12_TerB4')] p87 off: confinementstyle=ConfineIn formatcopy=TRUE lockcomponents=FALSE outline 3385,-1293.54 3533.48,-1293.54 3533.48,-1402 3385,-1402
RoomDefinition IDL_17_12_TerB3 [InComponentClass('IDL_17_12_TerB3')] p88 off: confinementstyle=ConfineIn formatcopy=TRUE lockcomponents=FALSE outline 3385,-1193.54 3533.48,-1193.54 3533.48,-1302 3385,-1302
RoomDefinition IDL_17_12_TerB2 [InComponentClass('IDL_17_12_TerB2')] p89 off: confinementstyle=ConfineIn formatcopy=TRUE lockcomponents=FALSE outline 3385,-1088.54 3533.48,-1088.54 3533.48,-1197 3385,-1197
RoomDefinition IDL_17_12_TerB1 [InComponentClass('IDL_17_12_TerB1')] p90 off: confinementstyle=ConfineIn formatcopy=TRUE lockcomponents=FALSE outline 3384.31,-981.07 3532.78,-981.07 3532.78,-1089.53 3384.31,-1089.53
RoomDefinition IDL_17_12_TerA71 [InComponentClass('IDL_17_12_TerA71')] p91 off: confinementstyle=ConfineIn formatcopy=TRUE lockcomponents=FALSE outline 5150,1104.7 5299.11,1104.7 5299.11,998 5150,998
RoomDefinition IDL_17_12_TerA70 [InComponentClass('IDL_17_12_TerA70')] p92 off: confinementstyle=ConfineIn formatcopy=TRUE lockcomponents=FALSE outline 5150,1209.7 5299.11,1209.7 5299.11,1103 5150,1103
RoomDefinition IDL_17_12_TerA69 [InComponentClass('IDL_17_12_TerA69')] p93 off: confinementstyle=ConfineIn formatcopy=TRUE lockcomponents=FALSE outline 5150,1314.7 5299.11,1314.7 5299.11,1208 5150,1208
RoomDefinition IDL_17_12_TerA68 [InComponentClass('IDL_17_12_TerA68')] p94 off: confinementstyle=ConfineIn formatcopy=TRUE lockcomponents=FALSE outline 5150,1419.7 5299.11,1419.7 5299.11,1313 5150,1313
RoomDefinition IDL_17_12_TerA67 [InComponentClass('IDL_17_12_TerA67')] p95 off: confinementstyle=ConfineIn formatcopy=TRUE lockcomponents=FALSE outline 5150,1524.7 5299.11,1524.7 5299.11,1418 5150,1418
RoomDefinition IDL_17_12_TerA66 [InComponentClass('IDL_17_12_TerA66')] p96 off: confinementstyle=ConfineIn formatcopy=TRUE lockcomponents=FALSE outline 5150,1629.7 5299.11,1629.7 5299.11,1523 5150,1523
RoomDefinition IDL_17_12_TerA65 [InComponentClass('IDL_17_12_TerA65')] p97 off: confinementstyle=ConfineIn formatcopy=TRUE lockcomponents=FALSE outline 5150,1734.7 5299.11,1734.7 5299.11,1628 5150,1628
RoomDefinition IDL_17_12_TerA64 [InComponentClass('IDL_17_12_TerA64')] p98 off: confinementstyle=ConfineIn formatcopy=TRUE lockcomponents=FALSE outline 5150,1839.7 5299.11,1839.7 5299.11,1733 5150,1733
RoomDefinition IDL_17_12_TerA63 [InComponentClass('IDL_17_12_TerA63')] p99 off: confinementstyle=ConfineIn formatcopy=TRUE lockcomponents=FALSE outline 5150,1944.7 5299.11,1944.7 5299.11,1838 5150,1838
RoomDefinition IDL_17_12_TerA62 [InComponentClass('IDL_17_12_TerA62')] p100 off: confinementstyle=ConfineIn formatcopy=TRUE lockcomponents=FALSE outline 5150,2049.7 5299.11,2049.7 5299.11,1943 5150,1943
RoomDefinition IDL_17_12_TerA61 [InComponentClass('IDL_17_12_TerA61')] p101 off: confinementstyle=ConfineIn formatcopy=TRUE lockcomponents=FALSE outline 5150,2157.7 5299.11,2157.7 5299.11,2051 5150,2051
RoomDefinition IDL_17_12_TerA60 [InComponentClass('IDL_17_12_TerA60')] p102 off: confinementstyle=ConfineIn formatcopy=TRUE lockcomponents=FALSE outline 5150,2262.7 5299.11,2262.7 5299.11,2156 5150,2156
RoomDefinition IDL_17_12_TerA59 [InComponentClass('IDL_17_12_TerA59')] p103 off: confinementstyle=ConfineIn formatcopy=TRUE lockcomponents=FALSE outline 5150,2367.7 5299.11,2367.7 5299.11,2261 5150,2261
RoomDefinition IDL_17_12_TerA58 [InComponentClass('IDL_17_12_TerA58')] p104 off: confinementstyle=ConfineIn formatcopy=TRUE lockcomponents=FALSE outline 5150,2472.7 5299.11,2472.7 5299.11,2366 5150,2366
RoomDefinition IDL_17_12_TerA57 [InComponentClass('IDL_17_12_TerA57')] p105 off: confinementstyle=ConfineIn formatcopy=TRUE lockcomponents=FALSE outline 5150,2577.7 5299.11,2577.7 5299.11,2471 5150,2471
RoomDefinition IDL_17_12_TerA56 [InComponentClass('IDL_17_12_TerA56')] p106 off: confinementstyle=ConfineIn formatcopy=TRUE lockcomponents=FALSE outline 5150,2682.7 5299.11,2682.7 5299.11,2576 5150,2576
RoomDefinition IDL_17_12_TerA55 [InComponentClass('IDL_17_12_TerA55')] p107 off: confinementstyle=ConfineIn formatcopy=TRUE lockcomponents=FALSE outline 5150,2787.7 5299.11,2787.7 5299.11,2681 5150,2681
RoomDefinition IDL_17_12_TerA54 [InComponentClass('IDL_17_12_TerA54')] p108 off: confinementstyle=ConfineIn formatcopy=TRUE lockcomponents=FALSE outline 5150,2892.7 5299.11,2892.7 5299.11,2786 5150,2786
RoomDefinition IDL_17_12_TerA53 [InComponentClass('IDL_17_12_TerA53')] p109 off: confinementstyle=ConfineIn formatcopy=TRUE lockcomponents=FALSE outline 5150,2997.7 5299.11,2997.7 5299.11,2891 5150,2891
RoomDefinition IDL_17_12_TerA52 [InComponentClass('IDL_17_12_TerA52')] p110 off: confinementstyle=ConfineIn formatcopy=TRUE lockcomponents=FALSE outline 5150,3102.7 5299.11,3102.7 5299.11,2996 5150,2996
RoomDefinition IDL_17_12_TerA51 [InComponentClass('IDL_17_12_TerA51')] p111 off: confinementstyle=ConfineIn formatcopy=TRUE lockcomponents=FALSE outline 5150,3207.7 5299.11,3207.7 5299.11,3101 5150,3101
RoomDefinition IDL_17_12_TerA50 [InComponentClass('IDL_17_12_TerA50')] p112 off: confinementstyle=ConfineIn formatcopy=TRUE lockcomponents=FALSE outline 5150,3312.7 5299.11,3312.7 5299.11,3206 5150,3206
RoomDefinition IDL_17_12_TerA49 [InComponentClass('IDL_17_12_TerA49')] p113 off: confinementstyle=ConfineIn formatcopy=TRUE lockcomponents=FALSE outline 5150,3417.7 5299.11,3417.7 5299.11,3311 5150,3311
RoomDefinition IDL_17_12_TerA48 [InComponentClass('IDL_17_12_TerA48')] p114 off: confinementstyle=ConfineIn formatcopy=TRUE lockcomponents=FALSE outline 5150,3522.7 5299.11,3522.7 5299.11,3416 5150,3416
RoomDefinition IDL_17_12_TerA47 [InComponentClass('IDL_17_12_TerA47')] p115 off: confinementstyle=ConfineIn formatcopy=TRUE lockcomponents=FALSE outline 5150,3627.7 5299.11,3627.7 5299.11,3521 5150,3521
RoomDefinition IDL_17_12_TerA46 [InComponentClass('IDL_17_12_TerA46')] p116 off: confinementstyle=ConfineIn formatcopy=TRUE lockcomponents=FALSE outline 5150,3730.7 5299.11,3730.7 5299.11,3624 5150,3624
RoomDefinition IDL_17_12_TerA45 [InComponentClass('IDL_17_12_TerA45')] p117 off: confinementstyle=ConfineIn formatcopy=TRUE lockcomponents=FALSE outline 5150,3835.7 5299.11,3835.7 5299.11,3729 5150,3729
RoomDefinition IDL_17_12_TerA44 [InComponentClass('IDL_17_12_TerA44')] p118 off: confinementstyle=ConfineIn formatcopy=TRUE lockcomponents=FALSE outline 5150,3940.7 5299.11,3940.7 5299.11,3834 5150,3834
RoomDefinition IDL_17_12_TerA43 [InComponentClass('IDL_17_12_TerA43')] p119 off: confinementstyle=ConfineIn formatcopy=TRUE lockcomponents=FALSE outline 4277.81,1122.74 4426.92,1122.74 4426.92,1016.03 4277.81,1016.03
RoomDefinition IDL_17_12_TerA42 [InComponentClass('IDL_17_12_TerA42')] p120 off: confinementstyle=ConfineIn formatcopy=TRUE lockcomponents=FALSE outline 4277.88,1245.7 4426.99,1245.7 4426.99,1139 4277.88,1139
RoomDefinition IDL_17_12_TerA41 [InComponentClass('IDL_17_12_TerA41')] p121 off: confinementstyle=ConfineIn formatcopy=TRUE lockcomponents=FALSE outline 4277.88,1345.7 4426.99,1345.7 4426.99,1239 4277.88,1239
RoomDefinition IDL_17_12_TerA40 [InComponentClass('IDL_17_12_TerA40')] p122 off: confinementstyle=ConfineIn formatcopy=TRUE lockcomponents=FALSE outline 4285,2235.7 4434.11,2235.7 4434.11,2129 4285,2129
RoomDefinition IDL_17_12_TerA39 [InComponentClass('IDL_17_12_TerA39')] p123 off: confinementstyle=ConfineIn formatcopy=TRUE lockcomponents=FALSE outline 4285,2340.7 4434.11,2340.7 4434.11,2234 4285,2234
RoomDefinition IDL_17_12_TerA38 [InComponentClass('IDL_17_12_TerA38')] p124 off: confinementstyle=ConfineIn formatcopy=TRUE lockcomponents=FALSE outline 4285,2445.7 4434.11,2445.7 4434.11,2339 4285,2339
RoomDefinition IDL_17_12_TerA37 [InComponentClass('IDL_17_12_TerA37')] p125 off: confinementstyle=ConfineIn formatcopy=TRUE lockcomponents=FALSE outline 4285,2550.7 4434.11,2550.7 4434.11,2444 4285,2444
RoomDefinition IDL_17_12_TerA36 [InComponentClass('IDL_17_12_TerA36')] p126 off: confinementstyle=ConfineIn formatcopy=TRUE lockcomponents=FALSE outline 4285,2655.7 4434.11,2655.7 4434.11,2549 4285,2549
RoomDefinition IDL_17_12_TerA35 [InComponentClass('IDL_17_12_TerA35')] p127 off: confinementstyle=ConfineIn formatcopy=TRUE lockcomponents=FALSE outline 4285,2760.7 4434.11,2760.7 4434.11,2654 4285,2654
RoomDefinition IDL_17_12_TerA34 [InComponentClass('IDL_17_12_TerA34')] p128 off: confinementstyle=ConfineIn formatcopy=TRUE lockcomponents=FALSE outline 4285,2865.7 4434.11,2865.7 4434.11,2759 4285,2759
RoomDefinition IDL_17_12_TerA33 [InComponentClass('IDL_17_12_TerA33')] p129 off: confinementstyle=ConfineIn formatcopy=TRUE lockcomponents=FALSE outline 4285,2970.7 4434.11,2970.7 4434.11,2864 4285,2864
RoomDefinition IDL_17_12_TerA32 [InComponentClass('IDL_17_12_TerA32')] p130 off: confinementstyle=ConfineIn formatcopy=TRUE lockcomponents=FALSE outline 4285,3245.7 4434.11,3245.7 4434.11,3139 4285,3139
RoomDefinition IDL_17_12_TerA31 [InComponentClass('IDL_17_12_TerA31')] p131 off: confinementstyle=ConfineIn formatcopy=TRUE lockcomponents=FALSE outline 4285,3353.7 4434.11,3353.7 4434.11,3247 4285,3247
RoomDefinition IDL_17_12_TerA30 [InComponentClass('IDL_17_12_TerA30')] p132 off: confinementstyle=ConfineIn formatcopy=TRUE lockcomponents=FALSE outline 4285,3458.7 4434.11,3458.7 4434.11,3352 4285,3352
RoomDefinition IDL_17_12_TerA29 [InComponentClass('IDL_17_12_TerA29')] p133 off: confinementstyle=ConfineIn formatcopy=TRUE lockcomponents=FALSE outline 4285,3563.7 4434.11,3563.7 4434.11,3457 4285,3457
RoomDefinition IDL_17_12_TerA28 [InComponentClass('IDL_17_12_TerA28')] p134 off: confinementstyle=ConfineIn formatcopy=TRUE lockcomponents=FALSE outline 4285,3668.7 4434.11,3668.7 4434.11,3562 4285,3562
RoomDefinition IDL_17_12_TerA27 [InComponentClass('IDL_17_12_TerA27')] p135 off: confinementstyle=ConfineIn formatcopy=TRUE lockcomponents=FALSE outline 4285,3773.7 4434.11,3773.7 4434.11,3667 4285,3667
RoomDefinition IDL_17_12_TerA26 [InComponentClass('IDL_17_12_TerA26')] p136 off: confinementstyle=ConfineIn formatcopy=TRUE lockcomponents=FALSE outline 4285,3878.7 4434.11,3878.7 4434.11,3772 4285,3772
RoomDefinition IDL_17_12_TerA25 [InComponentClass('IDL_17_12_TerA25')] p137 off: confinementstyle=ConfineIn formatcopy=TRUE lockcomponents=FALSE outline 4285,3983.7 4434.11,3983.7 4434.11,3877 4285,3877
RoomDefinition IDL_17_12_TerA24 [InComponentClass('IDL_17_12_TerA24')] p138 off: confinementstyle=ConfineIn formatcopy=TRUE lockcomponents=FALSE outline 4285,4088.7 4434.11,4088.7 4434.11,3982 4285,3982
RoomDefinition IDL_17_12_TerA23 [InComponentClass('IDL_17_12_TerA23')] p139 off: confinementstyle=ConfineIn formatcopy=TRUE lockcomponents=FALSE outline 3422.91,1146.18 3572.02,1146.18 3572.02,1039.48 3422.91,1039.48
RoomDefinition IDL_17_12_TerA22 [InComponentClass('IDL_17_12_TerA22')] p140 off: confinementstyle=ConfineIn formatcopy=TRUE lockcomponents=FALSE outline 3422.91,1251.18 3572.02,1251.18 3572.02,1144.48 3422.91,1144.48
RoomDefinition IDL_17_12_TerA21 [InComponentClass('IDL_17_12_TerA21')] p141 off: confinementstyle=ConfineIn formatcopy=TRUE lockcomponents=FALSE outline 3422.91,1356.18 3572.02,1356.18 3572.02,1249.48 3422.91,1249.48
RoomDefinition IDL_17_12_TerA20 [InComponentClass('IDL_17_12_TerA20')] p142 off: confinementstyle=ConfineIn formatcopy=TRUE lockcomponents=FALSE outline 3422.91,1461.18 3572.02,1461.18 3572.02,1354.48 3422.91,1354.48
RoomDefinition IDL_17_12_TerA19 [InComponentClass('IDL_17_12_TerA19')] p143 off: confinementstyle=ConfineIn formatcopy=TRUE lockcomponents=FALSE outline 3422.91,1566.18 3572.02,1566.18 3572.02,1459.48 3422.91,1459.48
RoomDefinition IDL_17_12_TerA18 [InComponentClass('IDL_17_12_TerA18')] p144 off: confinementstyle=ConfineIn formatcopy=TRUE lockcomponents=FALSE outline 3422.91,1671.18 3572.02,1671.18 3572.02,1564.48 3422.91,1564.48
RoomDefinition IDL_17_12_TerA17 [InComponentClass('IDL_17_12_TerA17')] p145 off: confinementstyle=ConfineIn formatcopy=TRUE lockcomponents=FALSE outline 3422.91,1776.18 3572.02,1776.18 3572.02,1669.48 3422.91,1669.48
RoomDefinition IDL_17_12_TerA16 [InComponentClass('IDL_17_12_TerA16')] p146 off: confinementstyle=ConfineIn formatcopy=TRUE lockcomponents=FALSE outline 3422.91,1879.18 3572.02,1879.18 3572.02,1772.48 3422.91,1772.48
RoomDefinition IDL_17_12_TerA15 [InComponentClass('IDL_17_12_TerA15')] p147 off: confinementstyle=ConfineIn formatcopy=TRUE lockcomponents=FALSE outline 3270.64,2048.55 3419.75,2048.55 3419.75,1941.85 3270.64,1941.85
RoomDefinition IDL_17_12_TerA14 [InComponentClass('IDL_17_12_TerA14')] p148 off: confinementstyle=ConfineIn formatcopy=TRUE lockcomponents=FALSE outline 3264.63,2268.49 3413.75,2268.49 3413.75,2161.79 3264.63,2161.79
RoomDefinition IDL_17_12_TerA13 [InComponentClass('IDL_17_12_TerA13')] p149 off: confinementstyle=ConfineIn formatcopy=TRUE lockcomponents=FALSE outline 3264.63,2373.49 3413.75,2373.49 3413.75,2266.79 3264.63,2266.79
RoomDefinition IDL_17_12_TerA12 [InComponentClass('IDL_17_12_TerA12')] p150 off: confinementstyle=ConfineIn formatcopy=TRUE lockcomponents=FALSE outline 3264.63,2478.49 3413.75,2478.49 3413.75,2371.79 3264.63,2371.79
RoomDefinition IDL_17_12_TerA11 [InComponentClass('IDL_17_12_TerA11')] p151 off: confinementstyle=ConfineIn formatcopy=TRUE lockcomponents=FALSE outline 3265,2661.7 3414.11,2661.7 3414.11,2555 3265,2555
RoomDefinition IDL_17_12_TerA10 [InComponentClass('IDL_17_12_TerA10')] p152 off: confinementstyle=ConfineIn formatcopy=TRUE lockcomponents=FALSE outline 3265,2856.7 3414.11,2856.7 3414.11,2750 3265,2750
RoomDefinition IDL_17_12_TerA9 [InComponentClass('IDL_17_12_TerA9')] p153 off: confinementstyle=ConfineIn formatcopy=TRUE lockcomponents=FALSE outline 3265,3056.7 3414.11,3056.7 3414.11,2950 3265,2950
RoomDefinition IDL_17_12_TerA8 [InComponentClass('IDL_17_12_TerA8')] p154 off: confinementstyle=ConfineIn formatcopy=TRUE lockcomponents=TRUE outline 3265,3321.7 3414.11,3321.7 3414.11,3215 3265,3215
RoomDefinition IDL_17_12_TerA7 [InComponentClass('IDL_17_12_TerA7')] p155 off: confinementstyle=ConfineIn formatcopy=TRUE lockcomponents=FALSE outline 3265,3426.7 3414.11,3426.7 3414.11,3320 3265,3320
RoomDefinition IDL_17_12_TerA6 [InComponentClass('IDL_17_12_TerA6')] p156 off: confinementstyle=ConfineIn formatcopy=TRUE lockcomponents=FALSE outline 3265,3531.7 3414.11,3531.7 3414.11,3425 3265,3425
RoomDefinition IDL_17_12_TerA5 [InComponentClass('IDL_17_12_TerA5')] p157 off: confinementstyle=ConfineIn formatcopy=TRUE lockcomponents=FALSE outline 3265,3636.7 3414.11,3636.7 3414.11,3530 3265,3530
RoomDefinition IDL_17_12_TerA4 [InComponentClass('IDL_17_12_TerA4')] p158 off: confinementstyle=ConfineIn formatcopy=TRUE lockcomponents=FALSE outline 3265,3741.7 3414.11,3741.7 3414.11,3635 3265,3635
RoomDefinition IDL_17_12_TerA3 [InComponentClass('IDL_17_12_TerA3')] p159 off: confinementstyle=ConfineIn formatcopy=TRUE lockcomponents=FALSE outline 3265,3846.7 3414.11,3846.7 3414.11,3740 3265,3740
RoomDefinition IDL_17_12_TerA2 [InComponentClass('IDL_17_12_TerA2')] p160 off: confinementstyle=ConfineIn formatcopy=TRUE lockcomponents=FALSE outline 3265,3951.7 3414.11,3951.7 3414.11,3845 3265,3845
RoomDefinition IDL_17_12_TerA1 [InComponentClass('IDL_17_12_TerA1')] p161 off: confinementstyle=ConfineIn formatcopy=TRUE lockcomponents=TRUE outline 3270,4062.94 3419.11,4062.94 3419.11,3956.24 3270,3956.24
RoutingLayers "RoutingLayers - Default - DEFAULT" [All] p1: top layer_v5=TRUE bottom layer_v5=TRUE
RoutingPriority "RoutingPriority - Default - DEFAULT" [All] p1: routingpriority=3
RoutingTopology "Default Routing Topology" [All] p1: topology=Shortest
RoutingVias "RoutingVias - Default - DEFAULT" [All] p1: holewidth=11.81 width=25.59 viastyle="Through Hole" minholewidth=11.81 minwidth=25.59 maxholewidth=11.81 maxwidth=25.59
SMDToCorner "SMDToCorner - Default - DEFAULT" [All] p1: distance=60000
SilkToSilkClearance [All] p1: silktosilkclearance=5
SilkToSolderMaskClearance [IsPad] p1: minsilkscreentomaskgap=5 clearancetoexposedcopper=TRUE
SolderMaskExpansion [All] p1: expansion=4
Width "Default Width" [All] p1: maxlimit=150 minlimit=3.94 preferedwidth=8
16 further rules are at their usual default settings.

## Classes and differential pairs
component class IDL_17_12_TerA72: CR_IDL_17_12_TerA72 R1R_IDL_17_12_TerA72 R2R_IDL_17_12_TerA72
component class IDL_17_12_J1: Jtop1 Jtop2 Jtop3
component class IDL_17_12_J2: Jbot1 Jbot2 Jbot3 Jbot4
component class IDL_17_12_TerA1: CR_IDL_17_12_TerA1 R1R_IDL_17_12_TerA1 R2R_IDL_17_12_TerA1
component class IDL_17_12_TerA2: CR_IDL_17_12_TerA2 R1R_IDL_17_12_TerA2 R2R_IDL_17_12_TerA2
component class IDL_17_12_TerA3: CR_IDL_17_12_TerA3 R1R_IDL_17_12_TerA3 R2R_IDL_17_12_TerA3
component class IDL_17_12_TerA4: CR_IDL_17_12_TerA4 R1R_IDL_17_12_TerA4 R2R_IDL_17_12_TerA4
component class IDL_17_12_TerA5: CR_IDL_17_12_TerA5 R1R_IDL_17_12_TerA5 R2R_IDL_17_12_TerA5
component class IDL_17_12_TerA6: CR_IDL_17_12_TerA6 R1R_IDL_17_12_TerA6 R2R_IDL_17_12_TerA6
component class IDL_17_12_TerA7: CR_IDL_17_12_TerA7 R1R_IDL_17_12_TerA7 R2R_IDL_17_12_TerA7
component class IDL_17_12_TerA8: CR_IDL_17_12_TerA8 R1R_IDL_17_12_TerA8 R2R_IDL_17_12_TerA8
component class IDL_17_12_TerA9: CR_IDL_17_12_TerA9 R1R_IDL_17_12_TerA9 R2R_IDL_17_12_TerA9
component class IDL_17_12_TerA10: CR_IDL_17_12_TerA10 R1R_IDL_17_12_TerA10 R2R_IDL_17_12_TerA10
component class IDL_17_12_TerA11: CR_IDL_17_12_TerA11 R1R_IDL_17_12_TerA11 R2R_IDL_17_12_TerA11
component class IDL_17_12_TerA12: CR_IDL_17_12_TerA12 R1R_IDL_17_12_TerA12 R2R_IDL_17_12_TerA12
component class IDL_17_12_TerA13: CR_IDL_17_12_TerA13 R1R_IDL_17_12_TerA13 R2R_IDL_17_12_TerA13
component class IDL_17_12_TerA14: CR_IDL_17_12_TerA14 R1R_IDL_17_12_TerA14 R2R_IDL_17_12_TerA14
component class IDL_17_12_TerA15: CR_IDL_17_12_TerA15 R1R_IDL_17_12_TerA15 R2R_IDL_17_12_TerA15
component class IDL_17_12_TerA16: CR_IDL_17_12_TerA16 R1R_IDL_17_12_TerA16 R2R_IDL_17_12_TerA16
component class IDL_17_12_TerA17: CR_IDL_17_12_TerA17 R1R_IDL_17_12_TerA17 R2R_IDL_17_12_TerA17
component class IDL_17_12_TerA18: CR_IDL_17_12_TerA18 R1R_IDL_17_12_TerA18 R2R_IDL_17_12_TerA18
component class IDL_17_12_TerA19: CR_IDL_17_12_TerA19 R1R_IDL_17_12_TerA19 R2R_IDL_17_12_TerA19
component class IDL_17_12_TerA20: CR_IDL_17_12_TerA20 R1R_IDL_17_12_TerA20 R2R_IDL_17_12_TerA20
component class IDL_17_12_TerA21: CR_IDL_17_12_TerA21 R1R_IDL_17_12_TerA21 R2R_IDL_17_12_TerA21
component class IDL_17_12_TerA22: CR_IDL_17_12_TerA22 R1R_IDL_17_12_TerA22 R2R_IDL_17_12_TerA22
component class IDL_17_12_TerA23: CR_IDL_17_12_TerA23 R1R_IDL_17_12_TerA23 R2R_IDL_17_12_TerA23
component class IDL_17_12_TerA24: CR_IDL_17_12_TerA24 R1R_IDL_17_12_TerA24 R2R_IDL_17_12_TerA24
component class IDL_17_12_TerA25: CR_IDL_17_12_TerA25 R1R_IDL_17_12_TerA25 R2R_IDL_17_12_TerA25
component class IDL_17_12_TerA26: CR_IDL_17_12_TerA26 R1R_IDL_17_12_TerA26 R2R_IDL_17_12_TerA26
component class IDL_17_12_TerA27: CR_IDL_17_12_TerA27 R1R_IDL_17_12_TerA27 R2R_IDL_17_12_TerA27
component class IDL_17_12_TerA28: CR_IDL_17_12_TerA28 R1R_IDL_17_12_TerA28 R2R_IDL_17_12_TerA28
component class IDL_17_12_TerA29: CR_IDL_17_12_TerA29 R1R_IDL_17_12_TerA29 R2R_IDL_17_12_TerA29
component class IDL_17_12_TerA30: CR_IDL_17_12_TerA30 R1R_IDL_17_12_TerA30 R2R_IDL_17_12_TerA30
component class IDL_17_12_TerA31: CR_IDL_17_12_TerA31 R1R_IDL_17_12_TerA31 R2R_IDL_17_12_TerA31
component class IDL_17_12_TerA32: CR_IDL_17_12_TerA32 R1R_IDL_17_12_TerA32 R2R_IDL_17_12_TerA32
component class IDL_17_12_TerA33: CR_IDL_17_12_TerA33 R1R_IDL_17_12_TerA33 R2R_IDL_17_12_TerA33
component class IDL_17_12_TerA34: CR_IDL_17_12_TerA34 R1R_IDL_17_12_TerA34 R2R_IDL_17_12_TerA34
component class IDL_17_12_TerA35: CR_IDL_17_12_TerA35 R1R_IDL_17_12_TerA35 R2R_IDL_17_12_TerA35
component class IDL_17_12_TerA36: CR_IDL_17_12_TerA36 R1R_IDL_17_12_TerA36 R2R_IDL_17_12_TerA36
component class IDL_17_12_TerA37: CR_IDL_17_12_TerA37 R1R_IDL_17_12_TerA37 R2R_IDL_17_12_TerA37
component class IDL_17_12_TerA38: CR_IDL_17_12_TerA38 R1R_IDL_17_12_TerA38 R2R_IDL_17_12_TerA38
component class IDL_17_12_TerA39: CR_IDL_17_12_TerA39 R1R_IDL_17_12_TerA39 R2R_IDL_17_12_TerA39
component class IDL_17_12_TerA40: CR_IDL_17_12_TerA40 R1R_IDL_17_12_TerA40 R2R_IDL_17_12_TerA40
component class IDL_17_12_TerA41: CR_IDL_17_12_TerA41 R1R_IDL_17_12_TerA41 R2R_IDL_17_12_TerA41
component class IDL_17_12_TerA42: CR_IDL_17_12_TerA42 R1R_IDL_17_12_TerA42 R2R_IDL_17_12_TerA42
component class IDL_17_12_TerA43: CR_IDL_17_12_TerA43 R1R_IDL_17_12_TerA43 R2R_IDL_17_12_TerA43
component class IDL_17_12_TerA44: CR_IDL_17_12_TerA44 R1R_IDL_17_12_TerA44 R2R_IDL_17_12_TerA44
component class IDL_17_12_TerA45: CR_IDL_17_12_TerA45 R1R_IDL_17_12_TerA45 R2R_IDL_17_12_TerA45
component class IDL_17_12_TerA46: CR_IDL_17_12_TerA46 R1R_IDL_17_12_TerA46 R2R_IDL_17_12_TerA46
component class IDL_17_12_TerA47: CR_IDL_17_12_TerA47 R1R_IDL_17_12_TerA47 R2R_IDL_17_12_TerA47
component class IDL_17_12_TerA48: CR_IDL_17_12_TerA48 R1R_IDL_17_12_TerA48 R2R_IDL_17_12_TerA48
component class IDL_17_12_TerA49: CR_IDL_17_12_TerA49 R1R_IDL_17_12_TerA49 R2R_IDL_17_12_TerA49
component class IDL_17_12_TerA50: CR_IDL_17_12_TerA50 R1R_IDL_17_12_TerA50 R2R_IDL_17_12_TerA50
component class IDL_17_12_TerA51: CR_IDL_17_12_TerA51 R1R_IDL_17_12_TerA51 R2R_IDL_17_12_TerA51
component class IDL_17_12_TerA52: CR_IDL_17_12_TerA52 R1R_IDL_17_12_TerA52 R2R_IDL_17_12_TerA52
component class IDL_17_12_TerA53: CR_IDL_17_12_TerA53 R1R_IDL_17_12_TerA53 R2R_IDL_17_12_TerA53
component class IDL_17_12_TerA54: CR_IDL_17_12_TerA54 R1R_IDL_17_12_TerA54 R2R_IDL_17_12_TerA54
component class IDL_17_12_TerA55: CR_IDL_17_12_TerA55 R1R_IDL_17_12_TerA55 R2R_IDL_17_12_TerA55
component class IDL_17_12_TerA56: CR_IDL_17_12_TerA56 R1R_IDL_17_12_TerA56 R2R_IDL_17_12_TerA56
component class IDL_17_12_TerA57: CR_IDL_17_12_TerA57 R1R_IDL_17_12_TerA57 R2R_IDL_17_12_TerA57
component class IDL_17_12_TerA58: CR_IDL_17_12_TerA58 R1R_IDL_17_12_TerA58 R2R_IDL_17_12_TerA58
component class IDL_17_12_TerA59: CR_IDL_17_12_TerA59 R1R_IDL_17_12_TerA59 R2R_IDL_17_12_TerA59
component class IDL_17_12_TerA60: CR_IDL_17_12_TerA60 R1R_IDL_17_12_TerA60 R2R_IDL_17_12_TerA60
component class IDL_17_12_TerA61: CR_IDL_17_12_TerA61 R1R_IDL_17_12_TerA61 R2R_IDL_17_12_TerA61
component class IDL_17_12_TerA62: CR_IDL_17_12_TerA62 R1R_IDL_17_12_TerA62 R2R_IDL_17_12_TerA62
component class IDL_17_12_TerA63: CR_IDL_17_12_TerA63 R1R_IDL_17_12_TerA63 R2R_IDL_17_12_TerA63
component class IDL_17_12_TerA64: CR_IDL_17_12_TerA64 R1R_IDL_17_12_TerA64 R2R_IDL_17_12_TerA64
component class IDL_17_12_TerA65: CR_IDL_17_12_TerA65 R1R_IDL_17_12_TerA65 R2R_IDL_17_12_TerA65
component class IDL_17_12_TerA66: CR_IDL_17_12_TerA66 R1R_IDL_17_12_TerA66 R2R_IDL_17_12_TerA66
component class IDL_17_12_TerA67: CR_IDL_17_12_TerA67 R1R_IDL_17_12_TerA67 R2R_IDL_17_12_TerA67
component class IDL_17_12_TerA68: CR_IDL_17_12_TerA68 R1R_IDL_17_12_TerA68 R2R_IDL_17_12_TerA68
component class IDL_17_12_TerA69: CR_IDL_17_12_TerA69 R1R_IDL_17_12_TerA69 R2R_IDL_17_12_TerA69
component class IDL_17_12_TerA70: CR_IDL_17_12_TerA70 R1R_IDL_17_12_TerA70 R2R_IDL_17_12_TerA70
component class IDL_17_12_TerA71: CR_IDL_17_12_TerA71 R1R_IDL_17_12_TerA71 R2R_IDL_17_12_TerA71
component class IDL_17_12_TerB1: CRB_IDL_17_12_TerB1 R1RB_IDL_17_12_TerB1 R2RB_IDL_17_12_TerB1
component class IDL_17_12_TerB2: CRB_IDL_17_12_TerB2 R1RB_IDL_17_12_TerB2 R2RB_IDL_17_12_TerB2
component class IDL_17_12_TerB3: CRB_IDL_17_12_TerB3 R1RB_IDL_17_12_TerB3 R2RB_IDL_17_12_TerB3
component class IDL_17_12_TerB4: CRB_IDL_17_12_TerB4 R1RB_IDL_17_12_TerB4 R2RB_IDL_17_12_TerB4
component class IDL_17_12_TerB5: CRB_IDL_17_12_TerB5 R1RB_IDL_17_12_TerB5 R2RB_IDL_17_12_TerB5
component class IDL_17_12_TerB6: CRB_IDL_17_12_TerB6 R1RB_IDL_17_12_TerB6 R2RB_IDL_17_12_TerB6
component class IDL_17_12_TerB7: CRB_IDL_17_12_TerB7 R1RB_IDL_17_12_TerB7 R2RB_IDL_17_12_TerB7
component class IDL_17_12_TerB8: CRB_IDL_17_12_TerB8 R1RB_IDL_17_12_TerB8 R2RB_IDL_17_12_TerB8
component class IDL_17_12_TerB9: CRB_IDL_17_12_TerB9 R1RB_IDL_17_12_TerB9 R2RB_IDL_17_12_TerB9
component class IDL_17_12_TerB10: CRB_IDL_17_12_TerB10 R1RB_IDL_17_12_TerB10 R2RB_IDL_17_12_TerB10
component class IDL_17_12_TerB11: CRB_IDL_17_12_TerB11 R1RB_IDL_17_12_TerB11 R2RB_IDL_17_12_TerB11
component class IDL_17_12_TerB12: CRB_IDL_17_12_TerB12 R1RB_IDL_17_12_TerB12 R2RB_IDL_17_12_TerB12
component class IDL_17_12_TerB13: CRB_IDL_17_12_TerB13 R1RB_IDL_17_12_TerB13 R2RB_IDL_17_12_TerB13
component class IDL_17_12_TerB14: CRB_IDL_17_12_TerB14 R1RB_IDL_17_12_TerB14 R2RB_IDL_17_12_TerB14
component class IDL_17_12_TerB15: CRB_IDL_17_12_TerB15 R1RB_IDL_17_12_TerB15 R2RB_IDL_17_12_TerB15
component class IDL_17_12_TerB16: CRB_IDL_17_12_TerB16 R1RB_IDL_17_12_TerB16 R2RB_IDL_17_12_TerB16
component class IDL_17_12_TerB17: CRB_IDL_17_12_TerB17 R1RB_IDL_17_12_TerB17 R2RB_IDL_17_12_TerB17
component class IDL_17_12_TerB18: CRB_IDL_17_12_TerB18 R1RB_IDL_17_12_TerB18 R2RB_IDL_17_12_TerB18
component class IDL_17_12_TerB19: CRB_IDL_17_12_TerB19 R1RB_IDL_17_12_TerB19 R2RB_IDL_17_12_TerB19
component class IDL_17_12_TerB20: CRB_IDL_17_12_TerB20 R1RB_IDL_17_12_TerB20 R2RB_IDL_17_12_TerB20
component class IDL_17_12_TerB21: CRB_IDL_17_12_TerB21 R1RB_IDL_17_12_TerB21 R2RB_IDL_17_12_TerB21
component class IDL_17_12_TerB22: CRB_IDL_17_12_TerB22 R1RB_IDL_17_12_TerB22 R2RB_IDL_17_12_TerB22
component class IDL_17_12_TerB23: CRB_IDL_17_12_TerB23 R1RB_IDL_17_12_TerB23 R2RB_IDL_17_12_TerB23
component class IDL_17_12_TerB24: CRB_IDL_17_12_TerB24 R1RB_IDL_17_12_TerB24 R2RB_IDL_17_12_TerB24
component class IDL_17_12_TerB25: CRB_IDL_17_12_TerB25 R1RB_IDL_17_12_TerB25 R2RB_IDL_17_12_TerB25
component class IDL_17_12_TerB26: CRB_IDL_17_12_TerB26 R1RB_IDL_17_12_TerB26 R2RB_IDL_17_12_TerB26
component class IDL_17_12_TerB27: CRB_IDL_17_12_TerB27 R1RB_IDL_17_12_TerB27 R2RB_IDL_17_12_TerB27
component class IDL_17_12_TerB28: CRB_IDL_17_12_TerB28 R1RB_IDL_17_12_TerB28 R2RB_IDL_17_12_TerB28
component class IDL_17_12_TerB29: CRB_IDL_17_12_TerB29 R1RB_IDL_17_12_TerB29 R2RB_IDL_17_12_TerB29
component class IDL_17_12_TerB30: CRB_IDL_17_12_TerB30 R1RB_IDL_17_12_TerB30 R2RB_IDL_17_12_TerB30
component class IDL_17_12_TerB31: CRB_IDL_17_12_TerB31 R1RB_IDL_17_12_TerB31 R2RB_IDL_17_12_TerB31
component class IDL_17_12_TerB32: CRB_IDL_17_12_TerB32 R1RB_IDL_17_12_TerB32 R2RB_IDL_17_12_TerB32
component class IDL_17_12_TerB33: CRB_IDL_17_12_TerB33 R1RB_IDL_17_12_TerB33 R2RB_IDL_17_12_TerB33
component class IDL_17_12_TerB34: CRB_IDL_17_12_TerB34 R1RB_IDL_17_12_TerB34 R2RB_IDL_17_12_TerB34
component class IDL_17_12_TerB35: CRB_IDL_17_12_TerB35 R1RB_IDL_17_12_TerB35 R2RB_IDL_17_12_TerB35
component class IDL_17_12_TerB36: CRB_IDL_17_12_TerB36 R1RB_IDL_17_12_TerB36 R2RB_IDL_17_12_TerB36
component class IDL_17_12_TerB37: CRB_IDL_17_12_TerB37 R1RB_IDL_17_12_TerB37 R2RB_IDL_17_12_TerB37
component class IDL_17_12_TerB38: CRB_IDL_17_12_TerB38 R1RB_IDL_17_12_TerB38 R2RB_IDL_17_12_TerB38
component class IDL_17_12_TerB39: CRB_IDL_17_12_TerB39 R1RB_IDL_17_12_TerB39 R2RB_IDL_17_12_TerB39
component class IDL_17_12_TerB40: CRB_IDL_17_12_TerB40 R1RB_IDL_17_12_TerB40 R2RB_IDL_17_12_TerB40
component class IDL_17_12_TerB41: CRB_IDL_17_12_TerB41 R1RB_IDL_17_12_TerB41 R2RB_IDL_17_12_TerB41
component class IDL_17_12_TerB42: CRB_IDL_17_12_TerB42 R1RB_IDL_17_12_TerB42 R2RB_IDL_17_12_TerB42
component class IDL_17_12_TerB43: CRB_IDL_17_12_TerB43 R1RB_IDL_17_12_TerB43 R2RB_IDL_17_12_TerB43
component class IDL_17_12_TerB44: CRB_IDL_17_12_TerB44 R1RB_IDL_17_12_TerB44 R2RB_IDL_17_12_TerB44
component class IDL_17_12_TerB45: CRB_IDL_17_12_TerB45 R1RB_IDL_17_12_TerB45 R2RB_IDL_17_12_TerB45
component class IDL_17_12_TerB46: CRB_IDL_17_12_TerB46 R1RB_IDL_17_12_TerB46 R2RB_IDL_17_12_TerB46
component class IDL_17_12_TerB47: CRB_IDL_17_12_TerB47 R1RB_IDL_17_12_TerB47 R2RB_IDL_17_12_TerB47
component class IDL_17_12_TerB48: CRB_IDL_17_12_TerB48 R1RB_IDL_17_12_TerB48 R2RB_IDL_17_12_TerB48
component class IDL_17_12_TerB49: CRB_IDL_17_12_TerB49 R1RB_IDL_17_12_TerB49 R2RB_IDL_17_12_TerB49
